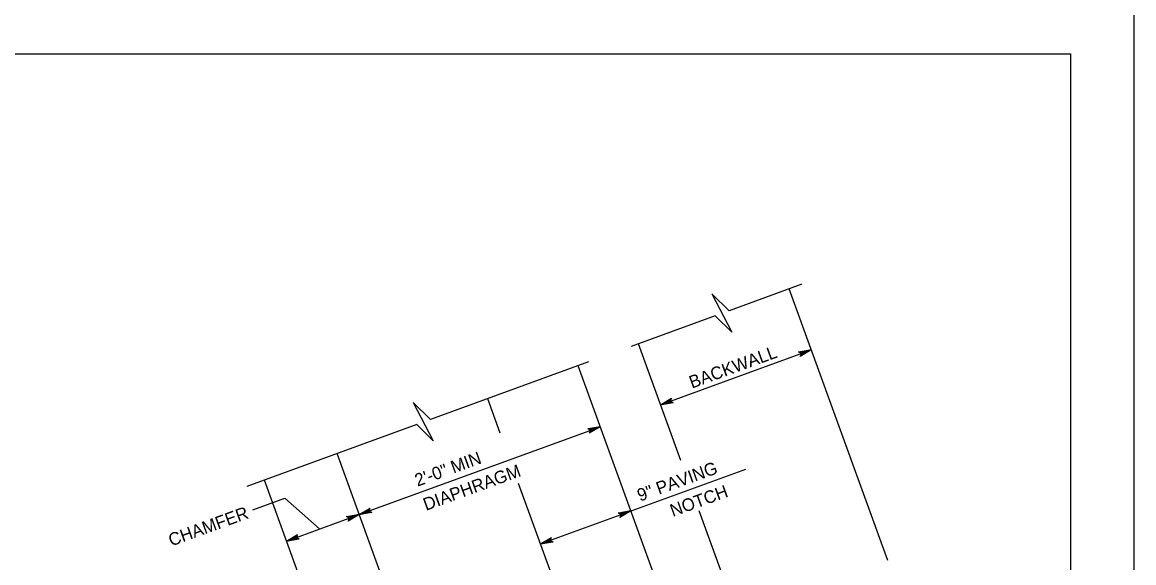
# Model space of a CAD drawing. Extents: x 638653 to 642302, y 298557 to 300414.
# Drawn here: x 641241.1 to 641505.2, y 299608.7 to 299737 of the extents above; entities that cross this region are included whole.
import ezdxf

# ---------------------------------------------------------------- set-up
doc = ezdxf.new("R2010")
doc.units = 0
doc.layers.add('1', color=7, linetype='Continuous')
doc.layers.add('PLT-BNDY', color=7, linetype='Continuous')

msp = doc.modelspace()

# ---------------------------------------------------------------- linework, layer by layer
at = {"layer": '1'}
for p, q in [((640704.16, 299729.52), (641490.16, 299729.52)), ((641490.16, 299729.52), (641490.16, 299165.52)), ((641426.27, 299674.82), (641409.02, 299668.54)), ((641446.72, 299609.26), (641423.26, 299673.72)), ((641405.72, 299667.34), (641385.71, 299660.06)), ((641397.53, 299633.02), (641387.46, 299660.69)), ((641392.72, 299646.23), (641428.53, 299659.26)), ((641375.61, 299656.38), (641338.1, 299642.73)), ((641431.68, 299494.65), (641373.14, 299655.48)), ((641354.64, 299639.46), (641351.66, 299647.66)), ((641334.79, 299641.53), (641294.44, 299626.84)), ((641321.12, 299620.17), (641378.4, 299641.02)), ((641346.02, 299551.74), (641315.85, 299634.63)), ((641364.2, 299613.2), (641413.01, 299630.97)), ((641310.77, 299594.92), (641298.6, 299628.35)), ((641379.83, 299570.24), (641358.97, 299627.57)), ((641295.89, 299621.33), (641303.45, 299624.08)), ((641303.45, 299624.08), (641311.72, 299616.75)), ((641303.87, 299613.89), (641321.12, 299620.17)), ((641417.87, 299577.15), (641401.89, 299621.03))]:
    msp.add_line(p, q, dxfattribs=at)
for points in [[(641409.02, 299668.54), (641404.87, 299672.55), (641409.63, 299663.48), (641405.72, 299667.34)], [(641428.53, 299659.26), (641425.91, 299657.71), (641425.99, 299657.83), (641426.08, 299657.94), (641426.1, 299658.06), (641426.12, 299658.17), (641426.1, 299658.27), (641426.08, 299658.37), (641426.03, 299658.46), (641425.98, 299658.55), (641425.89, 299658.62), (641425.8, 299658.69), (641425.67, 299658.73), (641425.53, 299658.76), (641428.53, 299659.26), (641425.67, 299658.73), (641425.8, 299658.69), (641428.53, 299659.26), (641425.89, 299658.62), (641425.98, 299658.55), (641428.53, 299659.26), (641426.03, 299658.46), (641426.08, 299658.37), (641428.53, 299659.26), (641426.1, 299658.27), (641426.12, 299658.17), (641428.53, 299659.26), (641426.1, 299658.06), (641426.08, 299657.94), (641428.53, 299659.26), (641425.99, 299657.83)], [(641338.1, 299642.73), (641333.94, 299646.73), (641338.71, 299637.67), (641334.79, 299641.53)], [(641392.72, 299646.23), (641395.33, 299647.77), (641395.25, 299647.66), (641395.17, 299647.55), (641395.15, 299647.43), (641395.13, 299647.32), (641395.15, 299647.22), (641395.17, 299647.12), (641395.22, 299647.03), (641395.27, 299646.94), (641395.36, 299646.87), (641395.45, 299646.79), (641395.58, 299646.76), (641395.72, 299646.72), (641392.72, 299646.23), (641395.58, 299646.76), (641395.45, 299646.79), (641392.72, 299646.23), (641395.36, 299646.87), (641395.27, 299646.94), (641392.72, 299646.23), (641395.22, 299647.03), (641395.17, 299647.12), (641392.72, 299646.23), (641395.15, 299647.22), (641395.13, 299647.32), (641392.72, 299646.23), (641395.15, 299647.43), (641395.17, 299647.55), (641392.72, 299646.23), (641395.25, 299647.66)], [(641378.4, 299641.02), (641375.79, 299639.47), (641375.87, 299639.58), (641375.95, 299639.7), (641375.97, 299639.81), (641376, 299639.93), (641375.98, 299640.03), (641375.96, 299640.13), (641375.91, 299640.21), (641375.86, 299640.3), (641375.77, 299640.38), (641375.68, 299640.45), (641375.54, 299640.49), (641375.41, 299640.52), (641378.4, 299641.02), (641375.54, 299640.49), (641375.68, 299640.45), (641378.4, 299641.02), (641375.77, 299640.38), (641375.86, 299640.3), (641378.4, 299641.02), (641375.91, 299640.21), (641375.96, 299640.13), (641378.4, 299641.02), (641375.98, 299640.03), (641376, 299639.93), (641378.4, 299641.02), (641375.97, 299639.81), (641375.95, 299639.7), (641378.4, 299641.02), (641375.87, 299639.58)], [(641321.12, 299620.17), (641323.73, 299621.71), (641323.65, 299621.6), (641323.57, 299621.48), (641323.55, 299621.37), (641323.53, 299621.25), (641323.54, 299621.15), (641323.56, 299621.06), (641323.61, 299620.97), (641323.66, 299620.88), (641323.75, 299620.81), (641323.84, 299620.73), (641323.98, 299620.7), (641324.11, 299620.66), (641321.12, 299620.17), (641323.98, 299620.7), (641323.84, 299620.73), (641321.12, 299620.17), (641323.75, 299620.81), (641323.66, 299620.88), (641321.12, 299620.17), (641323.61, 299620.97), (641323.56, 299621.06), (641321.12, 299620.17), (641323.54, 299621.15), (641323.53, 299621.25), (641321.12, 299620.17), (641323.55, 299621.37), (641323.57, 299621.48), (641321.12, 299620.17), (641323.65, 299621.6)], [(641321.12, 299620.17), (641318.51, 299618.62), (641318.59, 299618.73), (641318.67, 299618.85), (641318.69, 299618.96), (641318.71, 299619.08), (641318.69, 299619.18), (641318.68, 299619.28), (641318.62, 299619.36), (641318.57, 299619.45), (641318.48, 299619.53), (641318.39, 299619.6), (641318.26, 299619.64), (641318.12, 299619.67), (641321.12, 299620.17), (641318.26, 299619.64), (641318.39, 299619.6), (641321.12, 299620.17), (641318.48, 299619.53), (641318.57, 299619.45), (641321.12, 299620.17), (641318.62, 299619.36), (641318.68, 299619.28), (641321.12, 299620.17), (641318.69, 299619.18), (641318.71, 299619.08), (641321.12, 299620.17), (641318.69, 299618.96), (641318.67, 299618.85), (641321.12, 299620.17), (641318.59, 299618.73)], [(641385.68, 299621.02), (641383.07, 299619.47), (641383.15, 299619.59), (641383.23, 299619.7), (641383.25, 299619.82), (641383.27, 299619.93), (641383.26, 299620.03), (641383.24, 299620.13), (641383.19, 299620.22), (641383.14, 299620.31), (641383.05, 299620.38), (641382.96, 299620.45), (641382.82, 299620.49), (641382.69, 299620.52), (641385.68, 299621.02), (641382.82, 299620.49), (641382.96, 299620.45), (641385.68, 299621.02), (641383.05, 299620.38), (641383.14, 299620.31), (641385.68, 299621.02), (641383.19, 299620.22), (641383.24, 299620.13), (641385.68, 299621.02), (641383.26, 299620.03), (641383.27, 299619.93), (641385.68, 299621.02), (641383.25, 299619.82), (641383.23, 299619.7), (641385.68, 299621.02), (641383.15, 299619.59)], [(641303.87, 299613.89), (641306.48, 299615.43), (641306.4, 299615.32), (641306.32, 299615.2), (641306.3, 299615.09), (641306.27, 299614.98), (641306.29, 299614.88), (641306.31, 299614.78), (641306.36, 299614.69), (641306.41, 299614.6), (641306.5, 299614.53), (641306.59, 299614.45), (641306.73, 299614.42), (641306.86, 299614.38), (641303.87, 299613.89), (641306.73, 299614.42), (641306.59, 299614.45), (641303.87, 299613.89), (641306.5, 299614.53), (641306.41, 299614.6), (641303.87, 299613.89), (641306.36, 299614.69), (641306.31, 299614.78), (641303.87, 299613.89), (641306.29, 299614.88), (641306.27, 299614.98), (641303.87, 299613.89), (641306.3, 299615.09), (641306.32, 299615.2), (641303.87, 299613.89), (641306.4, 299615.32)], [(641364.2, 299613.2), (641366.81, 299614.75), (641366.73, 299614.63), (641366.65, 299614.52), (641366.63, 299614.4), (641366.61, 299614.29), (641366.62, 299614.19), (641366.64, 299614.09), (641366.69, 299614), (641366.74, 299613.91), (641366.83, 299613.84), (641366.92, 299613.77), (641367.06, 299613.73), (641367.19, 299613.7), (641364.2, 299613.2), (641367.06, 299613.73), (641366.92, 299613.77), (641364.2, 299613.2), (641366.83, 299613.84), (641366.74, 299613.91), (641364.2, 299613.2), (641366.69, 299614), (641366.64, 299614.09), (641364.2, 299613.2), (641366.62, 299614.19), (641366.61, 299614.29), (641364.2, 299613.2), (641366.63, 299614.4), (641366.65, 299614.52), (641364.2, 299613.2), (641366.73, 299614.63)]]:
    msp.add_lwpolyline(points, dxfattribs=at)
at = {"layer": 'PLT-BNDY'}
msp.add_lwpolyline([(640664.16, 299744.52), (641505.16, 299744.52), (641505.16, 299150.52), (640664.16, 299150.52)], close=True, dxfattribs=at)

# ---------------------------------------------------------------- texts
at = {"layer": '1'}
for s, p in [('BACKWALL', (641400.17, 299650.05)), ('2\'-0" MIN', (641334.97, 299626.77)), ('DIAPHRAGM', (641336.98, 299621.04)), ('9" PAVING', (641387.84, 299623.22)), ('NOTCH', (641395.63, 299619.59)), ('CHAMFER', (641276.47, 299612.58))]:
    msp.add_text(s, height=3, rotation=20, dxfattribs=at).set_placement(p)

doc.saveas('drawing.dxf')
